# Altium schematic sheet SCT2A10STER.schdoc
size 127 x 101 mm
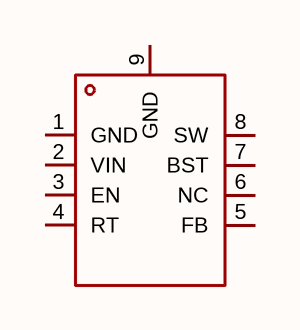
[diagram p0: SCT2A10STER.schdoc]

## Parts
U?  sct2a10ster  [ESOP-8_L4.9-W3.9-P1.27-LS6.0-BL-EP]  (value not drawn)

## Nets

Not connected (* = marked no-connect by the designer): U? 1(GND) 2(VIN) 3(EN) 4(RT) 5(FB) 6(NC) 7(BST) 8(SW) 9(GND)

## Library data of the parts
U? = sct2a10ster: 功能类型:降压型;工作电压:4.5V~85V;输出电压:800mV~24V;输出电流:600mA;输出类型:可调;; Manufacturer: SCT(芯洲科技); AddInBom: yes; ModelId: d3e00daa36c445139c055a3b9efb85d2; ModelName: ESOP-8_L4.9-W3.9-H1.6-LS6.0-P1.27; ModelTransform: 240.157,192.913,0,90,0,0,0,0,0; Function: 降压型; Output Current: 600mA; Frequency - Switching: 300kHz~800kHz; Synchronous Rectifier: 是; Number of Outputs: 1; Topology: 降压式; Quiescent Current: 100uA; Switch tube (built-in/external): 内置; Output Type: 可调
